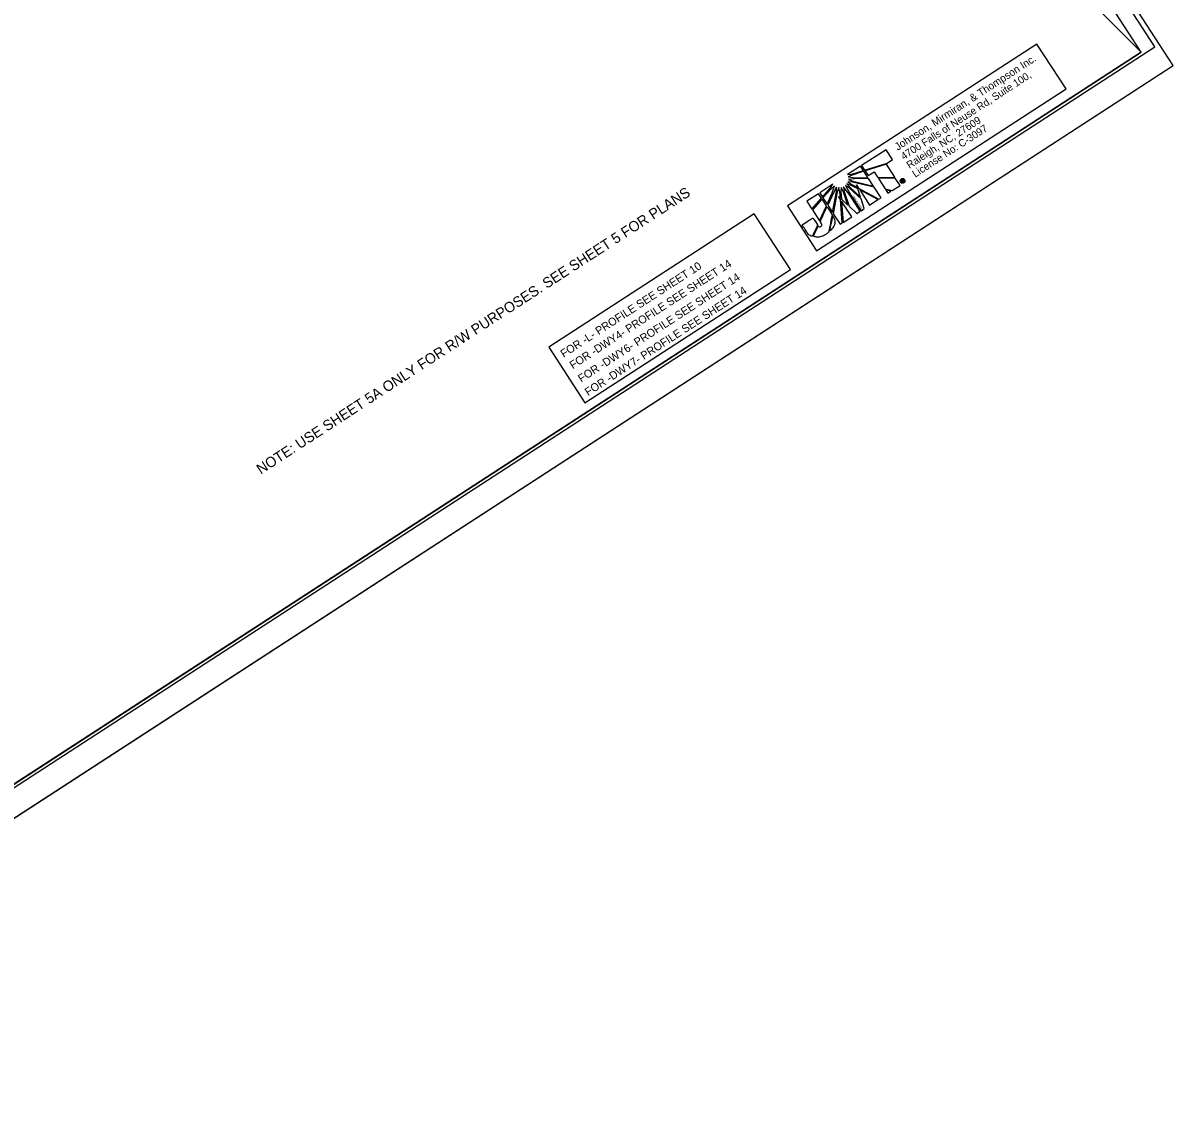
# Model space of a CAD drawing. Extents: x 555170 to 557181, y 503234 to 505074.
# Drawn here: x 556175 to 557181, y 503234 to 504189 of the extents above; entities that cross this region are included whole.
import ezdxf

# ---------------------------------------------------------------- set-up
doc = ezdxf.new("R2010")
doc.units = 0
for name, color, linetype in [('Exist Horizontal Alignment', 7, 'Continuous'), ('Old_Level_1', 7, 'Continuous'), ('Prop Horizontal Alignment', 7, 'Continuous'), ('Prop Superelevation Label', 7, 'Continuous'), ('Sheet North Arrow CELL', 7, 'Continuous'), ('Sheet Plot Border Outside CELL', 7, 'Continuous')]:
    doc.layers.add(name, color=color, linetype=linetype)

msp = doc.modelspace()

# ---------------------------------------------------------------- linework, layer by layer
at = {"layer": 'Exist Horizontal Alignment'}
msp.add_lwpolyline([(556581.9, 505074), (555169.6, 504156.8), (555768.7, 503234.3), (557181.1, 504151.5)], close=True, dxfattribs=at)
at = {"layer": 'Old_Level_1'}
for p, q in [((556930.1, 504077.8), (556908.6, 504063.9)), ((556935.8, 504069.1), (556930.1, 504077.8)), ((556907.9, 504063.3), (556896.5, 504056)), ((556910.3, 504059.7), (556907.9, 504063.3)), ((556908.6, 504063.9), (556911.2, 504060)), ((556911.3, 504059.8), (556931.2, 504066.1)), ((556930.4, 504065), (556911.7, 504059.2)), ((556937.7, 504053.7), (556930.4, 504065)), ((556931.2, 504066.1), (556935.8, 504069.1)), ((556896.5, 504056), (556900.3, 504056.5)), ((556900.5, 504055.6), (556897.1, 504054)), ((556897.1, 504054), (556903.6, 504053.2)), ((556900.3, 504056.5), (556910.3, 504059.7)), ((556910.8, 504058.9), (556900.5, 504055.6)), ((556903.6, 504053.2), (556914.2, 504053.4)), ((556914.2, 504053.4), (556910.8, 504058.9)), ((556911.2, 504060), (556911.3, 504059.8)), ((556911.7, 504059.2), (556911.7, 504059.2)), ((556911.7, 504059.2), (556914.4, 504055.1)), ((556914.4, 504055.1), (556919.6, 504058.5)), ((556919.6, 504058.5), (556922.8, 504053.6)), ((556922.8, 504053.6), (556937.7, 504053.7)), ((556938.2, 504052.9), (556923.4, 504052.7)), ((556942.4, 504046.6), (556938.2, 504052.9)), ((556883.5, 504047.6), (556872.1, 504040.1)), ((556874.4, 504036.4), (556881.5, 504044.4)), ((556882, 504043.6), (556874.9, 504035.6)), ((556881.5, 504044.4), (556883.5, 504047.6)), ((556885, 504046.1), (556882, 504043.6)), ((556883, 504040), (556885, 504046.1)), ((556886.9, 504045.1), (556884.3, 504040.6)), ((556886.7, 504041.1), (556886.9, 504045.1)), ((556888.9, 504044.6), (556887.5, 504040.8)), ((556889.8, 504040.6), (556888.9, 504044.6)), ((556890.9, 504044.7), (556890.6, 504040.8)), ((556892.7, 504041.4), (556890.9, 504044.7)), ((556898.6, 504037.6), (556892.9, 504045.3)), ((556892.9, 504045.3), (556893.6, 504041.2)), ((556894.6, 504046.4), (556899.3, 504038)), ((556898.1, 504044), (556894.6, 504046.4)), ((556895.9, 504047.9), (556898.4, 504044.9)), ((556899.6, 504046.6), (556895.9, 504047.9)), ((556896.8, 504049.8), (556900.2, 504047.3)), ((556900.9, 504049.5), (556896.8, 504049.8)), ((556902.4, 504052.4), (556897.2, 504051.8)), ((556897.2, 504051.8), (556901, 504050.3)), ((556908.3, 504034.7), (556898.1, 504044)), ((556898.4, 504044.9), (556907.7, 504036.3)), ((556905.3, 504043.6), (556899.6, 504046.6)), ((556900.2, 504047.3), (556905, 504044.7)), ((556919.7, 504044.9), (556900.9, 504049.5)), ((556901, 504050.3), (556919.1, 504046)), ((556914.8, 504052.5), (556902.4, 504052.4)), ((556905, 504044.7), (556904.2, 504047.1)), ((556904.2, 504047.1), (556906.1, 504044.1)), ((556907.7, 504036.3), (556905.3, 504043.6)), ((556906.1, 504044.1), (556923.9, 504034.6)), ((556919.1, 504046), (556914.8, 504052.5)), ((556925.7, 504035.8), (556919.7, 504044.9)), ((556923.4, 504052.7), (556929.3, 504043.6)), ((556929.3, 504043.6), (556935.5, 504042.1)), ((556935.5, 504042.1), (556942.4, 504046.6)), ((556943.4, 504050.9), (556944.1, 504051.3)), ((556944.4, 504049.3), (556943.4, 504050.9)), ((556943.5, 504052.2), (556943.7, 504051.9)), ((556943.7, 504051.9), (556943.5, 504052.2)), ((556944.2, 504051), (556944, 504050.8)), ((556944, 504050.8), (556944.2, 504050.5)), ((556944.1, 504051.3), (556944.1, 504051.4)), ((556944.1, 504051.3), (556944.2, 504051)), ((556944.2, 504051), (556944.1, 504051.3)), ((556944.3, 504051), (556944.2, 504051)), ((556944.2, 504050.5), (556944.5, 504050.6)), ((556944.7, 504050.4), (556944.4, 504050.2)), ((556944.4, 504050.2), (556944.8, 504049.6)), ((556944.8, 504049.6), (556944.4, 504049.3)), ((556944.5, 504050.6), (556944.7, 504050.4)), ((556944.7, 504050.4), (556944.5, 504050.6)), ((556944.5, 504050.6), (556944.5, 504050.6)), ((556944.7, 504050.4), (556944.7, 504050.4)), ((556945.5, 504049.1), (556945.7, 504048.8)), ((556945.7, 504048.8), (556945.5, 504049.1)), ((556945.5, 504049.1), (556945.5, 504049.1)), ((556945.7, 504048.8), (556945.7, 504048.8)), ((556871, 504039.3), (556860.8, 504032.7)), ((556865.2, 504025.9), (556873.6, 504035.4)), ((556874.1, 504034.7), (556865.7, 504025.2)), ((556873.6, 504035.4), (556871, 504039.3)), ((556872.1, 504040.1), (556874.4, 504036.4)), ((556877.9, 504028.8), (556874.1, 504034.7)), ((556874.9, 504035.6), (556878.5, 504030.1)), ((556878.5, 504030.1), (556883, 504040)), ((556884.3, 504040.6), (556879.1, 504029.2)), ((556883.3, 504022.9), (556886.7, 504041.1)), ((556887.5, 504040.8), (556884, 504021.8)), ((556890.2, 504034.1), (556888.4, 504036.8)), ((556888.4, 504036.8), (556890.2, 504035.3)), ((556890.2, 504035.3), (556889.8, 504040.6)), ((556891.7, 504013.6), (556890.2, 504034.1)), ((556890.6, 504040.8), (556891.1, 504034.5)), ((556891.1, 504034.5), (556896.7, 504029.4)), ((556896.7, 504029.4), (556892.7, 504041.4)), ((556893.6, 504041.2), (556897.9, 504028.3)), ((556907.4, 504024), (556898.6, 504037.6)), ((556899.3, 504038), (556908.2, 504024.4)), ((556923, 504034.1), (556907.1, 504042.6)), ((556907.1, 504042.6), (556915.7, 504029.4)), ((556911, 504026.3), (556908.3, 504034.7)), ((556915.7, 504029.4), (556923, 504034.1)), ((556923.9, 504034.6), (556925.7, 504035.8)), ((556934.4, 504041.5), (556929.9, 504042.6)), ((556929.9, 504042.6), (556931.8, 504039.7)), ((556931.8, 504039.7), (556934.4, 504041.5)), ((556860.8, 504032.7), (556865.2, 504025.9)), ((556865.7, 504025.2), (556871.9, 504015.7)), ((556871.9, 504015.7), (556877.9, 504028.8)), ((556879.1, 504029.2), (556883.3, 504022.9)), ((556900.1, 504019.1), (556891.2, 504032.7)), ((556891.2, 504032.7), (556892.5, 504014.1)), ((556897.9, 504028.3), (556904.6, 504022.1)), ((556904.6, 504022.1), (556907.4, 504024)), ((556908.2, 504024.4), (556911, 504026.3)), ((556884, 504021.8), (556890, 504012.5)), ((556890, 504012.5), (556891.7, 504013.6)), ((556892.5, 504014.1), (556900.1, 504019.1))]:
    msp.add_line(p, q, dxfattribs=at)
msp.add_lwpolyline([(556869.4, 503989.2), (557087.5, 504130.9), (557062, 504170.2), (556843.9, 504028.6)], close=True, dxfattribs=at)
for points in [[(556930.1, 504077.8), (556908.6, 504063.9), (556911.2, 504060), (556911.3, 504059.8), (556931.2, 504066.1), (556935.8, 504069.1), (556930.1, 504077.8)], [(556900.3, 504056.5), (556910.3, 504059.7), (556907.9, 504063.3), (556896.5, 504056), (556900.3, 504056.5)], [(556911.7, 504059.2), (556911.7, 504059.2), (556914.4, 504055.1), (556919.6, 504058.5), (556922.8, 504053.6), (556937.7, 504053.7), (556930.4, 504065), (556911.7, 504059.2)], [(556897.1, 504054), (556903.6, 504053.2), (556914.2, 504053.4), (556910.8, 504058.9), (556900.5, 504055.6), (556897.1, 504054)], [(556923.4, 504052.7), (556929.3, 504043.6), (556935.5, 504042.1), (556942.4, 504046.6), (556938.2, 504052.9), (556923.4, 504052.7), (556923.4, 504052.7)], [(556881.5, 504044.4), (556883.5, 504047.6), (556872.1, 504040.1), (556874.4, 504036.4), (556881.5, 504044.4)], [(556874.9, 504035.6), (556878.5, 504030.1), (556883, 504040), (556885, 504046.1), (556882, 504043.6), (556874.9, 504035.6)], [(556879.1, 504029.2), (556883.3, 504022.9), (556886.7, 504041.1), (556886.9, 504045.1), (556884.3, 504040.6), (556879.1, 504029.2)], [(556888.9, 504044.6), (556887.5, 504040.8), (556884, 504021.8), (556890, 504012.5), (556891.7, 504013.6), (556890.2, 504034.1), (556888.4, 504036.8), (556890.2, 504035.3), (556889.8, 504040.6), (556888.9, 504044.6)], [(556890.9, 504044.7), (556890.6, 504040.8), (556891.1, 504034.5), (556896.7, 504029.4), (556892.7, 504041.4), (556890.9, 504044.7)], [(556893.6, 504041.2), (556897.9, 504028.3), (556904.6, 504022.1), (556907.4, 504024), (556898.6, 504037.6), (556892.9, 504045.3), (556893.6, 504041.2)], [(556894.6, 504046.4), (556899.3, 504038), (556908.2, 504024.4), (556911, 504026.3), (556908.3, 504034.7), (556898.1, 504044), (556894.6, 504046.4)], [(556895.9, 504047.9), (556898.4, 504044.9), (556907.7, 504036.3), (556905.3, 504043.6), (556899.6, 504046.6), (556895.9, 504047.9)], [(556896.8, 504049.8), (556900.2, 504047.3), (556905, 504044.7), (556904.2, 504047.1), (556906.1, 504044.1), (556923.9, 504034.6), (556925.7, 504035.8), (556919.7, 504044.9), (556900.9, 504049.5), (556896.8, 504049.8)], [(556897.2, 504051.8), (556901, 504050.3), (556919.1, 504046), (556914.8, 504052.5), (556902.4, 504052.4), (556897.2, 504051.8)], [(556945.5, 504050.6), (556945.6, 504050.5), (556945.6, 504050.4), (556945.6, 504050.4), (556945.8, 504050.2), (556945.5, 504050)], [(556865.2, 504025.9), (556873.6, 504035.4), (556871, 504039.3), (556860.8, 504032.7), (556865.2, 504025.9)], [(556871.9, 504015.7), (556877.9, 504028.8), (556874.1, 504034.7), (556865.7, 504025.2), (556871.9, 504015.7)], [(556915.7, 504029.4), (556923, 504034.1), (556907.1, 504042.6), (556915.7, 504029.4)], [(556931.8, 504039.7), (556931.8, 504039.7), (556934.4, 504041.5), (556929.9, 504042.6), (556931.8, 504039.7)], [(556892.5, 504014.1), (556900.1, 504019.1), (556891.2, 504032.7), (556892.5, 504014.1)], [(556635.2, 503905), (556666.8, 503856.3), (556846.4, 503972.9), (556814.7, 504021.7), (556635.1, 503905.1)]]:
    msp.add_lwpolyline(points, dxfattribs=at)
for points, degree in [([(556945.7, 504048.8), (556945.2, 504048.5), (556944.7, 504048.4), (556944.1, 504048.5), (556943.6, 504048.6), (556943.1, 504048.9), (556942.8, 504049.4), (556942.5, 504049.9), (556942.4, 504050.4), (556942.6, 504050.9), (556942.7, 504051.5), (556943, 504051.9), (556943.5, 504052.2)], 3), ([(556943.7, 504051.9), (556943.3, 504051.7), (556943, 504051.3), (556942.9, 504050.9), (556942.8, 504050.4), (556942.9, 504050), (556943.2, 504049.6), (556943.4, 504049.2), (556943.8, 504049), (556944.2, 504048.9), (556944.7, 504048.8), (556945.1, 504048.9), (556945.5, 504049.1)], 3), ([(556943.5, 504052.2), (556943.9, 504052.5), (556944.5, 504052.6), (556945, 504052.5), (556945.6, 504052.4), (556946, 504052.1), (556946.3, 504051.7)], 3), ([(556945.5, 504049.1), (556945.9, 504049.4), (556946.1, 504049.7), (556946.2, 504050.2), (556946.3, 504050.6), (556946.2, 504051.1), (556946, 504051.4), (556945.7, 504051.8), (556945.3, 504052.1), (556944.9, 504052.2), (556944.5, 504052.2), (556944.1, 504052.2), (556943.7, 504051.9)], 3), ([(556944.1, 504051.4), (556944.5, 504051.6), (556944.8, 504051.6), (556945, 504051.3), (556945.1, 504051.1), (556945.2, 504051), (556945.1, 504050.8)], 3), ([(556944.5, 504050.6), (556944.7, 504050.8), (556944.8, 504050.9), (556944.7, 504051.1), (556944.6, 504051.2), (556944.5, 504051.2), (556944.3, 504051)], 3), ([(556945, 504050.5), (556944.9, 504050.5), (556944.8, 504050.5), (556944.7, 504050.4)], 2), ([(556945.5, 504050), (556945.4, 504050.1), (556945.3, 504050.1), (556945.2, 504050.3), (556945.1, 504050.4), (556945.1, 504050.5), (556945, 504050.5)], 3), ([(556945.1, 504050.8), (556945.2, 504050.8), (556945.4, 504050.7), (556945.5, 504050.6)], 2), ([(556946.3, 504051.7), (556946.6, 504051.2), (556946.7, 504050.7), (556946.6, 504050.1), (556946.5, 504049.6), (556946.2, 504049.1), (556945.7, 504048.8)], 3), ([(556873.1, 504010.6), (556872.5, 504010.2), (556871.8, 504010.2), (556870.8, 504011.2), (556870.8, 504011.2), (556866.5, 504001.9), (556866.5, 504001.9), (556870.3, 504001), (556874.8, 504001.9), (556877.8, 504003.9), (556878.6, 504004.4), (556879.2, 504004.9), (556879.9, 504005.6), (556879.9, 504005.6), (556882.9, 504021.1), (556882.9, 504021.1), (556882.9, 504021.1), (556878.5, 504027.9), (556878.5, 504027.9), (556878.5, 504027.9), (556872.5, 504014.8), (556872.5, 504014.8), (556874.2, 504012.2), (556874, 504011.1), (556873.1, 504010.6)], 3), ([(556873.1, 504010.6), (556872.5, 504010.2), (556871.8, 504010.2), (556870.8, 504011.2), (556870.8, 504011.2), (556866.5, 504001.9), (556866.5, 504001.9), (556870.3, 504001), (556874.8, 504001.9), (556877.8, 504003.9), (556878.6, 504004.4), (556879.2, 504004.9), (556879.9, 504005.6), (556879.9, 504005.6), (556882.9, 504021.1), (556882.9, 504021.1), (556882.9, 504021.1), (556878.5, 504027.9), (556878.5, 504027.9), (556878.5, 504027.9), (556872.5, 504014.8), (556872.5, 504014.8), (556874.2, 504012.2), (556874, 504011.1), (556873.1, 504010.6)], 3), ([(556866.1, 504018.1), (556866.1, 504018.1), (556856.7, 504012), (556856.7, 504012), (556856.7, 504012), (556860.6, 504006.1), (556860.6, 504006.1), (556860.6, 504006.1), (556861, 504005.5), (556861, 504005.5), (556862.2, 504003.6), (556863.7, 504002.5), (556865.6, 504002), (556865.6, 504002), (556870.3, 504011.8), (556870.2, 504011.9), (556870.2, 504011.9), (556866.1, 504018.1), (556866.1, 504018.1)], 3), ([(556883.6, 504020), (556883.6, 504020), (556881, 504006.6), (556881, 504006.6), (556884.3, 504010.1), (556886.5, 504015.2), (556883.6, 504020)], 3)]:
    msp.add_open_spline(points, degree=degree, dxfattribs=at)
at = {"layer": 'Prop Horizontal Alignment'}
msp.add_line((555768.7, 503234.3), (557181.1, 504151.5), dxfattribs=at)
at = {"layer": 'Prop Superelevation Label'}
msp.add_lwpolyline([(555838.5, 503433.5), (555757.6, 503602.9), (555641.4, 503854.9), (555665.1, 503867.4), (555636.4, 503915.7), (555617.1, 503909), (555456.4, 504257.6), (555437.1, 504299.2), (556413.5, 504934.8), (556427.1, 504820.4), (556498.5, 504667.6), (556631.8, 504743), (556936.9, 504379.3), (557153.2, 504163.2), (555896, 503346.8)], close=True, dxfattribs=at)
at = {"layer": 'Sheet North Arrow CELL'}
msp.add_lwpolyline([(556590.4, 505052.7), (555192.8, 504145.1), (555767.4, 503260.2), (557165.1, 504167.9)], close=True, dxfattribs=at)
at = {"layer": 'Sheet Plot Border Outside CELL'}
msp.add_lwpolyline([(556581.3, 505043.8), (555323.3, 504226.8), (555895.2, 503346.2), (557153.2, 504163.2)], close=True, dxfattribs=at)

# ---------------------------------------------------------------- texts
at = {"layer": 'Old_Level_1'}
for s, height, rotation, p in [('Johnson, Mirmiran, & Thompson Inc.', 6.645, 33.0007, (556940.3, 504076.8)), ('4700 Falls of Neuse Rd, Suite 100, ', 6.455, 33.0007, (556945.6, 504068.6)), ('Raleigh, NC, 27609', 6.455, 33.0007, (556950.6, 504060.9)), ('License No: C-3097', 6.455, 33.0007, (556955.6, 504053.2)), ('NOTE: USE SHEET 5A ONLY FOR R/W PURPOSES. SEE SHEET 5 FOR PLANS', 9.1, 33.0007, (556383.3, 503793.5)), ('www.jmt.com', 1.614, 303.0007, (556900.9, 504037.1)), ('FOR -L- PROFILE SEE SHEET 10', 7, 33.0007, (556648.2, 503895.6)), ('FOR -DWY4- PROFILE SEE SHEET 14', 7, 33.0007, (556656.2, 503885.6)), ('FOR -DWY6- PROFILE SEE SHEET 14', 7, 33.0007, (556663.6, 503873.9)), ('FOR -DWY7- PROFILE SEE SHEET 14', 7, 33.0007, (556669.5, 503862.1))]:
    msp.add_text(s, height=height, rotation=rotation, dxfattribs=at).set_placement(p)

doc.saveas('drawing.dxf')
